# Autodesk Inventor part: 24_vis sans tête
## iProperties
Shininess: 20.0
Length Units: 11270
Angle Units: 11279
Time Units: 11290
Mass Units: 11283
Length Display Precision: 3
Angle Display Precision: 2
Created: 2000-10
Part Number: 24_vis sans tête
Material: Par défaut
Document SubType Name: Modélisation
Density: 0.0
Volumn: 0.0
Area: 0.0
PropertySet Name: Model Information
Control State: 0
Master: False
Checked Out: False
Author: Laurent GAUTHERON
